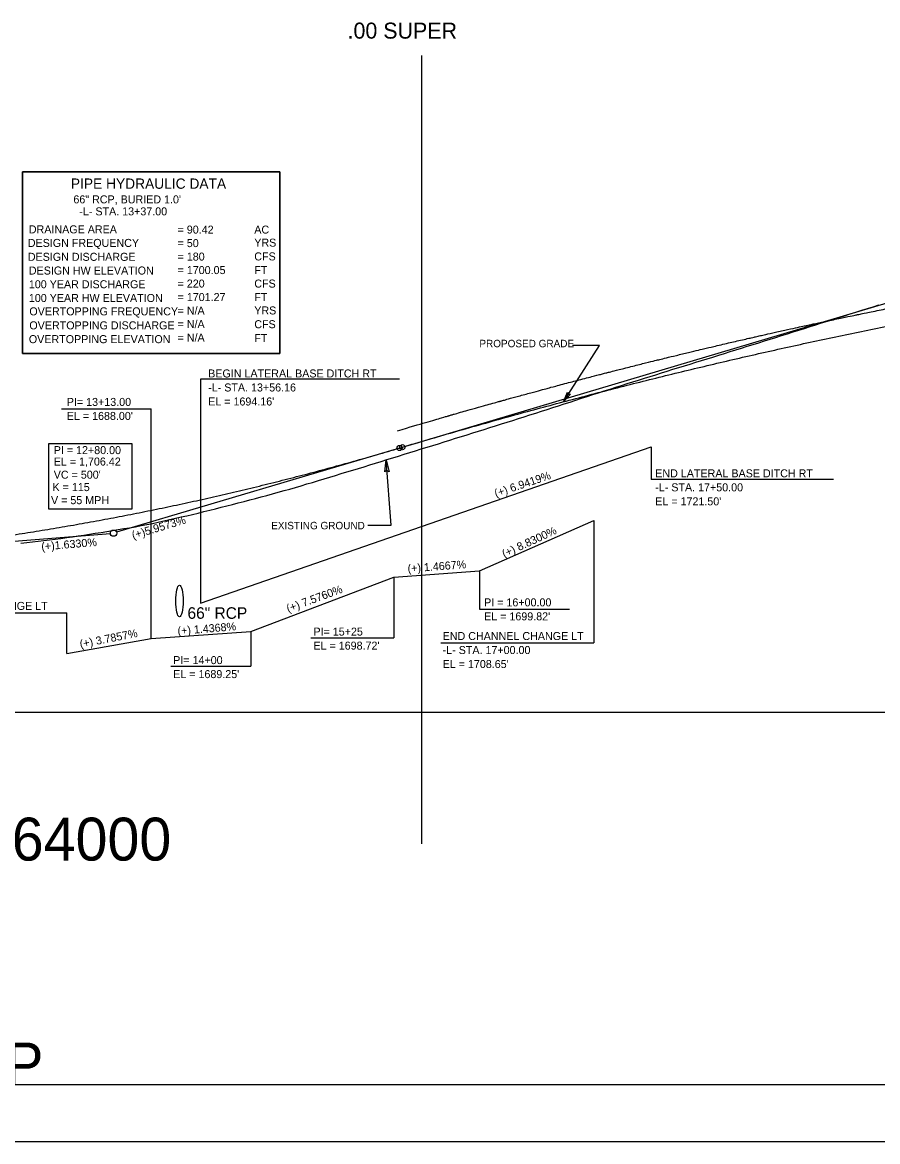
# Model space of a CAD drawing. Extents: x 498575 to 532350, y 405181 to 484585.
# Drawn here: x 506019 to 506767, y 483234 to 484213 of the extents above; entities that cross this region are included whole.
import ezdxf

# ---------------------------------------------------------------- set-up
doc = ezdxf.new("R2010")
doc.units = 0
for name, color, linetype in [('Exist Profile Cell', 7, 'Continuous'), ('Exist Vertical Profile Ground Line', 7, 'Continuous'), ('Prop Drainage Structure Pipe Welded Steel 54in Label', 7, 'Continuous'), ('Prop Grid Mask', 7, 'Continuous'), ('Prop PFL Text', 7, 'Continuous'), ('Prop Vertical Profile Curve Label', 7, 'Continuous'), ('Prop Vertical Profile Ditch Grade Left', 7, 'Continuous'), ('Prop Vertical Profile Ditch Grade Left Label', 7, 'Continuous'), ('Prop Vertical Profile Ditch Grade Right', 7, 'Continuous'), ('Prop Vertical Profile Ditch Grade Right Label', 7, 'Continuous'), ('Prop Vertical Profile Grade', 7, 'Continuous'), ('Prop Vertical Profile Grade Label', 7, 'Continuous'), ('Prop VPI Label', 7, 'Continuous'), ('Scratch_Level_4', 7, 'Continuous'), ('Scratch_Level_5', 7, 'Continuous'), ('Sheet Data Text CELL', 7, 'Continuous')]:
    doc.layers.add(name, color=color, linetype=linetype)

msp = doc.modelspace()

# ---------------------------------------------------------------- linework, layer by layer
at = {"layer": 'Exist Profile Cell'}
msp.add_line((505856.74, 483233.71), (526056.74, 483233.71), dxfattribs=at)
at = {"layer": 'Exist Vertical Profile Ground Line'}
for points in [[(506313.15, 483822.41), (506318.15, 483823.92), (506323.15, 483825.51), (506328.15, 483827.07), (506333.15, 483828.61), (506338.15, 483830.16), (506343.15, 483831.72), (506348.15, 483833.26), (506353.15, 483834.81), (506358.15, 483836.38), (506363.15, 483837.93), (506368.15, 483839.47), (506373.15, 483841.01), (506378.15, 483842.56), (506383.15, 483844.07), (506388.15, 483845.66), (506393.15, 483847.23), (506398.15, 483848.81), (506403.15, 483850.35), (506408.15, 483851.92), (506413.15, 483853.44), (506418.15, 483855.01), (506423.15, 483856.56), (506428.15, 483858.13), (506433.15, 483859.71), (506438.15, 483861.31), (506443.15, 483862.9), (506448.15, 483864.49), (506453.15, 483866.09), (506458.15, 483867.66), (506463.15, 483869.24), (506468.15, 483870.81), (506473.15, 483872.38), (506478.15, 483873.98), (506483.15, 483875.59), (506488.15, 483877.18), (506493.15, 483878.84), (506498.15, 483880.46), (506503.15, 483882.13), (506508.15, 483883.78), (506513.15, 483885.39), (506518.15, 483887.01), (506523.15, 483888.62), (506528.15, 483890.18), (506533.15, 483891.8), (506538.15, 483893.38), (506543.15, 483894.98), (506548.15, 483896.59), (506553.15, 483898.18), (506558.15, 483899.77), (506563.15, 483901.34), (506568.15, 483902.88), (506573.15, 483904.44), (506578.15, 483906.02), (506583.15, 483907.59), (506588.15, 483909.14), (506593.15, 483910.65), (506598.15, 483912.22), (506603.15, 483913.77), (506608.15, 483915.31), (506613.15, 483916.8), (506618.15, 483918.35), (506623.15, 483919.88), (506628.15, 483921.43), (506633.15, 483923.02), (506638.15, 483924.6), (506643.15, 483926.19), (506648.15, 483927.74), (506653.15, 483929.28), (506658.15, 483930.86), (506663.15, 483932.41), (506668.15, 483933.92), (506673.15, 483935.48), (506678.15, 483937.06), (506683.15, 483938.63), (506688.15, 483940.25), (506693.15, 483941.82), (506698.15, 483943.4), (506703.15, 483944.96), (506708.15, 483946.52), (506713.15, 483948.1), (506718.15, 483949.69), (506723.15, 483951.23), (506728.15, 483952.8), (506733.15, 483954.39), (506738.15, 483955.99), (506743.15, 483957.56), (506748.15, 483959.15), (506753.15, 483960.74), (506758.15, 483962.35), (506763.15, 483963.91), (506768.15, 483965.46)], [(506018.15, 483757.04), (506023.15, 483757.62), (506028.15, 483758.2), (506033.15, 483758.75), (506038.15, 483759.31), (506043.15, 483759.92), (506048.15, 483760.56), (506053.15, 483761.26), (506058.15, 483761.92), (506063.15, 483762.64), (506068.15, 483763.36), (506073.15, 483764.13), (506078.15, 483764.92), (506083.15, 483765.72), (506088.15, 483766.49), (506093.15, 483767.33), (506098.15, 483768.16), (506103.15, 483768.97), (506108.15, 483769.8), (506113.15, 483770.62), (506118.15, 483771.5), (506123.15, 483772.39), (506128.15, 483773.37), (506133.15, 483774.38), (506138.15, 483775.46), (506143.15, 483776.62), (506148.15, 483777.79), (506153.15, 483778.9), (506158.15, 483780.01), (506163.15, 483781.12), (506168.15, 483782.26), (506173.15, 483783.41), (506178.15, 483784.66), (506183.15, 483785.93), (506188.15, 483787.2), (506193.15, 483788.45), (506198.15, 483789.73), (506203.15, 483791.01), (506208.15, 483792.28), (506213.15, 483793.56), (506218.15, 483794.87), (506223.15, 483796.19), (506228.15, 483797.53), (506233.15, 483798.86), (506238.15, 483800.21), (506243.15, 483801.58), (506248.15, 483803), (506253.15, 483804.43), (506258.15, 483805.87), (506263.15, 483807.35), (506268.15, 483808.83), (506273.15, 483810.24), (506278.15, 483811.84), (506283.15, 483813.34), (506288.15, 483814.84), (506293.15, 483816.36), (506298.15, 483817.87), (506303.15, 483819.38), (506308.15, 483820.87), (506313.15, 483822.41)]]:
    msp.add_lwpolyline(points, dxfattribs=at)
at = {"layer": 'Prop Drainage Structure Pipe Welded Steel 54in Label'}
msp.add_ellipse((506156.7, 483706.52), major_axis=(0, 13.75), ratio=0.236364, dxfattribs=at)
at = {"layer": 'Prop Grid Mask'}
for points in [[(506019.47, 484081.91), (506244.47, 484081.91), (506244.47, 483922.91), (506019.47, 483922.91)], [(506042.37, 483787.13), (506115.38, 483787.13), (506115.38, 483843.91), (506042.37, 483843.91)]]:
    msp.add_lwpolyline(points, close=True, dxfattribs=at)
at = {"layer": 'Prop PFL Text'}
for p, q in [((506492.34, 483880.73), (506523.87, 483929.92)), ((506523.87, 483929.92), (506500.45, 483929.92)), ((506341.83, 483772.87), (506337.35, 483829.91)), ((506321.47, 483772.87), (506341.83, 483772.87))]:
    msp.add_line(p, q, dxfattribs=at)
for points in [[(506498.45, 483887.52), (506492.34, 483880.73), (506495.82, 483889.24), (506496.56, 483887.41)], [(506336.37, 483819.35), (506337.34, 483829.91), (506340.02, 483819.58), (506338.06, 483820.77)]]:
    msp.add_lwpolyline(points, close=True, dxfattribs=at)
at = {"layer": 'Prop Vertical Profile Curve Label'}
for centre in [(506349.08, 483840.3), (506351.58, 483841.05)]:
    msp.add_circle(centre, 2.25, dxfattribs=at)
at = {"layer": 'Prop Vertical Profile Ditch Grade Left'}
msp.add_lwpolyline([(506058.23, 483660.46), (506132.08, 483673.71), (506219.08, 483679.96), (506344.08, 483727.31), (506419.08, 483732.81), (506519.08, 483776.96)], dxfattribs=at)
at = {"layer": 'Prop Vertical Profile Ditch Grade Left Label'}
for p, q in [((506053.7, 483874.54), (506132.08, 483874.54)), ((506132.08, 483673.71), (506132.08, 483874.54)), ((506519.08, 483776.96), (506519.08, 483669.88)), ((506344.08, 483727.31), (506344.08, 483674.41)), ((506419.08, 483732.81), (506419.08, 483699.39)), ((505905.91, 483696.18), (506058.23, 483696.18)), ((506058.23, 483660.46), (506058.23, 483696.18)), ((506419.08, 483699.39), (506497.71, 483699.39)), ((506219.08, 483679.96), (506219.08, 483649.5)), ((506271.68, 483674.41), (506344.08, 483674.41)), ((506385.23, 483669.88), (506519.08, 483669.88)), ((506149.07, 483649.5), (506219.08, 483649.5))]:
    msp.add_line(p, q, dxfattribs=at)
at = {"layer": 'Prop Vertical Profile Ditch Grade Right'}
msp.add_line((506175.24, 483704.51), (506569.08, 483841.21), dxfattribs=at)
at = {"layer": 'Prop Vertical Profile Ditch Grade Right Label'}
for p, q in [((506349.12, 483900.4), (506175.24, 483900.4)), ((506175.24, 483900.4), (506175.24, 483704.51)), ((506569.08, 483841.21), (506569.08, 483812.74)), ((506728.41, 483812.74), (506569.08, 483812.74))]:
    msp.add_line(p, q, dxfattribs=at)
at = {"layer": 'Prop Vertical Profile Grade'}
msp.add_line((506349.08, 483840.3), (506351.58, 483841.05), dxfattribs=at)
for points in [[(506351.58, 483841.05), (506396.48, 483854.19), (506441.38, 483866.88), (506486.28, 483879.11), (506531.18, 483890.88), (506576.08, 483902.2), (506620.98, 483913.06), (506665.88, 483923.46), (506710.78, 483933.4), (506755.68, 483942.89), (506800.58, 483951.92), (506845.48, 483960.49), (506890.38, 483968.6), (506935.28, 483976.26), (506980.18, 483983.46), (507025.08, 483990.2), (507069.98, 483996.48), (507114.88, 484002.31), (507159.78, 484007.68), (507204.68, 484012.59), (507249.58, 484017.05), (507294.48, 484021.05), (507339.38, 484024.59), (507384.28, 484027.67), (507429.18, 484030.29), (507474.08, 484032.46), (507518.98, 484034.17), (507563.88, 484035.42), (507608.78, 484036.22), (507653.68, 484036.56), (507698.58, 484036.44), (507743.48, 484035.86), (507788.38, 484034.83), (507833.28, 484033.33), (507878.18, 484031.39), (507923.08, 484028.98), (507967.98, 484026.11), (508012.88, 484022.79), (508057.78, 484019.01), (508102.68, 484014.78), (508147.58, 484010.09), (508192.48, 484004.93), (508237.38, 483999.33), (508282.28, 483993.26), (508327.18, 483986.74), (508372.08, 483979.76), (508416.98, 483972.32), (508461.88, 483964.42), (508506.78, 483956.07), (508551.68, 483947.26), (508596.58, 483937.99)], [(505849.08, 483745.42), (505859.08, 483746.26), (505869.08, 483747.14), (505879.08, 483748.07), (505889.08, 483749.04), (505899.08, 483750.05), (505909.08, 483751.1), (505919.08, 483752.2), (505929.08, 483753.34), (505939.08, 483754.52), (505949.08, 483755.75), (505959.08, 483757.02), (505969.08, 483758.33), (505979.08, 483759.69), (505989.08, 483761.09), (505999.08, 483762.54), (506009.08, 483764.02), (506019.08, 483765.55), (506029.08, 483767.13), (506039.08, 483768.74), (506049.08, 483770.4), (506059.08, 483772.1), (506069.08, 483773.85), (506079.08, 483775.64), (506089.08, 483777.47), (506099.08, 483779.35), (506109.08, 483781.27), (506119.08, 483783.23), (506129.08, 483785.24), (506139.08, 483787.29), (506149.08, 483789.38), (506159.08, 483791.51), (506169.08, 483793.69), (506179.08, 483795.91), (506189.08, 483798.18), (506199.08, 483800.49), (506209.08, 483802.84), (506219.08, 483805.23), (506229.08, 483807.67), (506239.08, 483810.15), (506249.08, 483812.68), (506259.08, 483815.25), (506269.08, 483817.86), (506279.08, 483820.51), (506289.08, 483823.21), (506299.08, 483825.95), (506309.08, 483828.73), (506319.08, 483831.56), (506329.08, 483834.43), (506339.08, 483837.35), (506349.08, 483840.3)]]:
    msp.add_spline(points, degree=3, dxfattribs=at)
at = {"layer": 'Prop VPI Label'}
for p, q in [((506351.58, 483841.05), (507471.44, 484174.62)), ((506349.08, 483840.3), (506101.71, 483766.62)), ((505849.08, 483745.42), (506096.34, 483765.61))]:
    msp.add_line(p, q, dxfattribs=at)
msp.add_circle((506099.08, 483765.84), 2.75, dxfattribs=at)
at = {"layer": 'Scratch_Level_4'}
for p, q in [((506368.26, 484183.71), (506368.26, 483494.24)), ((505856.74, 483283.71), (512195.09, 483283.71))]:
    msp.add_line(p, q, dxfattribs=at)
at = {"layer": 'Scratch_Level_5'}
msp.add_line((513582.6, 483608.99), (498575.1, 483608.99), dxfattribs=at)
msp.add_open_spline([(506347.36, 483855.44), (506358.71, 483858.77), (506372.9, 483862.92), (506387.8, 483867.28), (506391.39, 483868.33), (506392.17, 483868.56), (506392.24, 483868.58), (506392.27, 483868.59), (506392.28, 483868.59), (506392.3, 483868.6), (506392.4, 483868.63), (506392.68, 483868.71), (506393.31, 483868.89), (506395.28, 483869.47), (506397.07, 483869.99), (506404.23, 483872.06), (506409.95, 483873.68), (506421.39, 483876.9), (506427.1, 483878.48), (506434.23, 483880.46), (506435.66, 483880.86), (506437.17, 483881.28), (506437.26, 483881.3), (506437.39, 483881.34), (506437.44, 483881.35), (506437.53, 483881.38), (506437.75, 483881.44), (506438.33, 483881.6), (506439.58, 483881.95), (506443.51, 483883.04), (506452.81, 483885.6), (506464.25, 483888.72), (506472.84, 483891.04), (506478.57, 483892.58), (506481.44, 483893.35), (506495.77, 483897.17), (506507.24, 483900.19), (506521.6, 483903.91), (506524.47, 483904.65), (506528.78, 483905.76), (506530.22, 483906.13), (506533.09, 483906.86), (506540.28, 483908.7), (506553.22, 483911.97), (506564.73, 483914.85), (506573.37, 483916.98), (506576.25, 483917.69), (506582.01, 483919.11), (506590.65, 483921.22), (506602.19, 483924), (506610.84, 483926.07), (506616.61, 483927.44), (506619.5, 483928.12), (506633.94, 483931.53), (506645.5, 483934.2), (506658.51, 483937.17), (506659.96, 483937.5), (506662.85, 483938.15), (506664.3, 483938.48), (506668.64, 483939.46), (506677.32, 483941.41), (506688.91, 483943.99), (506697.6, 483945.89), (506703.4, 483947.15), (506706.3, 483947.78), (506715, 483949.66), (506726.6, 483952.14), (506739.66, 483954.89), (506746.92, 483956.4), (506749.83, 483957), (506751.28, 483957.3), (506755.64, 483958.2), (506770.17, 483961.18), (506784.71, 483964.09), (506799.27, 483966.95), (506802.18, 483967.52), (506808.01, 483968.65), (506816.74, 483970.34), (506828.4, 483972.56), (506837.15, 483974.2), (506842.98, 483975.28), (506845.9, 483975.82), (506854.65, 483977.44), (506866.33, 483979.57), (506878.01, 483981.65), (506886.77, 483983.2), (506889.69, 483983.71), (506895.54, 483984.73), (506898.46, 483985.24), (506913.08, 483987.76), (506924.78, 483989.74), (506948.2, 483993.59), (506959.92, 483995.47), (506974.57, 483997.77), (506977.51, 483998.22), (506983.37, 483999.13), (506992.17, 484000.48), (507000.97, 484001.81), (507012.71, 484003.56), (507018.58, 484004.42), (507030.32, 484006.12), (507042.07, 484007.79), (507053.83, 484009.42), (507062.64, 484010.63), (507065.58, 484011.03), (507071.47, 484011.82), (507086.17, 484013.79), (507100.88, 484015.68), (507115.6, 484017.52), (507118.55, 484017.88), (507124.44, 484018.61), (507133.27, 484019.68), (507145.06, 484021.08), (507153.9, 484022.11), (507159.79, 484022.78), (507162.74, 484023.12), (507171.59, 484024.11), (507183.38, 484025.42), (507195.18, 484026.68), (507204.04, 484027.61), (507206.99, 484027.92), (507212.89, 484028.52), (507221.75, 484029.42), (507233.56, 484030.59), (507242.42, 484031.44), (507248.33, 484032), (507251.28, 484032.27), (507266.05, 484033.64), (507277.87, 484034.69), (507292.66, 484035.95), (507295.61, 484036.19), (507301.53, 484036.68), (507310.4, 484037.41), (507322.23, 484038.34), (507331.11, 484039.01), (507337.02, 484039.45), (507339.98, 484039.67), (507348.86, 484040.32), (507360.7, 484041.15), (507372.54, 484041.94), (507384.39, 484042.71), (507390.31, 484043.08), (507402.15, 484043.8), (507408.08, 484044.15), (507419.93, 484044.82), (507425.85, 484045.14), (507443.63, 484046.08), (507455.49, 484046.65), (507473.27, 484047.44), (507479.2, 484047.7), (507491.06, 484048.18), (507496.99, 484048.4), (507508.85, 484048.84), (507514.78, 484049.04), (507526.64, 484049.43), (507538.51, 484049.79), (507550.37, 484050.1), (507562.24, 484050.39), (507568.17, 484050.53), (507585.97, 484050.89), (507597.84, 484051.08), (507621.57, 484051.38), (507633.44, 484051.48), (507657.18, 484051.58), (507669.05, 484051.58), (507692.78, 484051.49), (507704.65, 484051.4), (507722.45, 484051.19), (507728.39, 484051.11), (507740.25, 484050.92), (507746.19, 484050.82), (507763.99, 484050.46), (507775.85, 484050.18), (507799.58, 484049.52), (507811.44, 484049.14), (507829.24, 484048.5), (507835.17, 484048.28), (507847.03, 484047.8), (507858.88, 484047.31), (507870.74, 484046.76), (507882.59, 484046.19), (507888.52, 484045.89), (507900.37, 484045.28), (507906.3, 484044.96), (507918.15, 484044.29), (507924.07, 484043.95), (507941.84, 484042.88), (507953.69, 484042.12), (507971.45, 484040.91), (507977.37, 484040.5), (507989.21, 484039.65), (507995.13, 484039.21), (508006.96, 484038.31), (508012.88, 484037.84), (508024.71, 484036.9), (508036.53, 484035.92), (508048.36, 484034.91), (508057.23, 484034.12), (508060.18, 484033.86), (508066.09, 484033.33), (508074.96, 484032.52), (508086.77, 484031.41), (508095.63, 484030.55), (508101.54, 484029.97), (508104.49, 484029.67), (508119.25, 484028.19), (508131.05, 484026.96), (508145.8, 484025.37), (508148.75, 484025.05), (508154.65, 484024.4), (508163.5, 484023.41), (508175.29, 484022.07), (508184.13, 484021.03), (508190.02, 484020.33), (508192.97, 484019.98), (508201.81, 484018.92), (508213.59, 484017.48), (508225.36, 484016), (508234.19, 484014.86), (508237.13, 484014.48), (508243.02, 484013.72), (508257.73, 484011.79), (508272.42, 484009.79), (508287.12, 484007.73), (508290.05, 484007.31), (508295.93, 484006.48), (508304.74, 484005.22), (508316.48, 484003.5), (508325.28, 484002.19), (508331.15, 484001.31), (508334.09, 484000.86), (508342.89, 483999.53), (508354.61, 483997.72), (508366.34, 483995.87), (508378.05, 483993.99), (508383.91, 483993.04), (508395.62, 483991.12), (508401.48, 483990.15), (508413.18, 483988.18), (508419.03, 483987.19), (508436.57, 483984.17), (508448.26, 483982.12), (508462.86, 483979.49), (508465.78, 483978.96), (508471.61, 483977.9), (508480.37, 483976.3), (508492.04, 483974.13), (508502.24, 483972.2), (508506.98, 483971.3), (508508.8, 483970.96), (508509.34, 483970.85), (508509.53, 483970.82), (508509.89, 483970.75), (508510.8, 483970.57), (508511.7, 483970.4), (508518.24, 483969.15), (508524.07, 483968.03), (508535.73, 483965.77), (508541.57, 483964.62), (508548.87, 483963.14), (508550.33, 483962.85), (508552.53, 483962.4), (508553.44, 483962.21), (508554.4, 483962.01), (508554.63, 483961.97), (508554.72, 483961.95), (508554.76, 483961.94), (508554.9, 483961.91), (508555.35, 483961.82), (508558.7, 483961.13), (508573.54, 483958.06), (508588.02, 483955.07), (508599.61, 483952.68)], degree=3, dxfattribs=at)
at = {"layer": 'Sheet Data Text CELL'}
msp.add_lwpolyline([(506019.47, 483922.91), (506244.47, 483922.91), (506244.47, 484081.91), (506019.47, 484081.91)], close=True, dxfattribs=at)

# ---------------------------------------------------------------- texts
at = {"layer": 'Exist Profile Cell'}
for s, p in [('1037.664000', (505856.74, 483479.51)), ('NOGAP', (505856.74, 483282.87))]:
    msp.add_text(s, height=37.5, dxfattribs=at).set_placement(p)
at = {"layer": 'Prop Drainage Structure Pipe Welded Steel 54in Label'}
msp.add_text('66" RCP', height=10.125, dxfattribs=at).set_placement((506163.74, 483690.91))
at = {"layer": 'Prop PFL Text'}
for s, p in [('PROPOSED GRADE', (506418.94, 483928.42)), ('EXISTING GROUND', (506236.93, 483769.22))]:
    msp.add_text(s, height=6.5157, dxfattribs=at).set_placement(p)
at = {"layer": 'Prop Vertical Profile Curve Label'}
for s, p in [("VC = 500'", (506046.81, 483813.47)), ('K = 115', (506045.75, 483802.63)), ('V = 55 MPH ', (506044.44, 483791.2))]:
    msp.add_text(s, height=7, dxfattribs=at).set_placement(p)
at = {"layer": 'Prop Vertical Profile Ditch Grade Left Label'}
for s, rotation, p in [('PI= 13+13.00', 360, (506058.22, 483877.1)), ("EL = 1688.00'", 360, (506058.22, 483864.85)), ('(+) 8.8300%', 24.83808, (506440.67, 483744.17)), ('(+) 1.4667%', 4.20337, (506356.42, 483731.43)), ('(+) 7.5760%', 20.15498, (506251.78, 483696.37)), ('BEGIN CHANNEL CHANGE LT', 360, (505908.89, 483698.7)), ('PI = 16+00.00', 360, (506423.06, 483701.81)), ("EL = 1699.82'", 360, (506423.06, 483689.56)), ('(+) 1.4368%', 4.60611, (506155.33, 483676.83)), ('(+) 3.7857%', 11.04903, (506070.24, 483665.37)), ('PI= 15+25', 360, (506273.85, 483676.23)), ('END CHANNEL CHANGE LT', 360, (506386.81, 483672.37)), ("EL = 1698.72'", 360, (506273.85, 483663.98)), ('-L- STA. 17+00.00', 360, (506386.81, 483660.12)), ('PI= 14+00', 360, (506151.24, 483651.32)), ("EL = 1708.65'", 360, (506386.81, 483647.87)), ("EL = 1689.25'", 360, (506151.24, 483639.07))]:
    msp.add_text(s, height=7, rotation=rotation, dxfattribs=at).set_placement(p)
at = {"layer": 'Prop Vertical Profile Ditch Grade Right Label'}
for s, rotation, p in [('BEGIN LATERAL BASE DITCH RT', 360, (506181.84, 483902)), ('-L- STA. 13+56.16', 360, (506181.84, 483889.75)), ("EL = 1694.16'", 360, (506181.84, 483877.5)), ('END LATERAL BASE DITCH RT', 360, (506572.67, 483814.66)), ('(+) 6.9419%', 18.64339, (506433.43, 483797.08)), ('-L- STA. 17+50.00', 360, (506572.67, 483802.41)), ("EL = 1721.50'", 360, (506572.67, 483790.16))]:
    msp.add_text(s, height=7, rotation=rotation, dxfattribs=at).set_placement(p)
at = {"layer": 'Prop Vertical Profile Grade Label'}
for s, rotation, p in [('(+)5.9573%', 16.58697, (506116.24, 483760.51)), ('(+)1.6330%', 4.66793, (506036.24, 483750.67))]:
    msp.add_text(s, height=7, rotation=rotation, dxfattribs=at).set_placement(p)
at = {"layer": 'Prop VPI Label'}
for s, p in [('PI = 12+80.00', (506046.81, 483834.96)), ('EL = 1,706.42', (506046.81, 483824.96))]:
    msp.add_text(s, height=7, dxfattribs=at).set_placement(p)
at = {"layer": 'Scratch_Level_4'}
msp.add_text('.00 SUPER', height=14, dxfattribs=at).set_placement((506303.66, 484198.32))
at = {"layer": 'Sheet Data Text CELL'}
for s, height, p in [('PIPE HYDRAULIC DATA', 8.9997, (506061.77, 484067.02)), ('DRAINAGE AREA', 6.9999, (506025.05, 484028.01)), ('= 90.42', 7, (506155.08, 484027.81)), ('AC', 7, (506222.14, 484027.81)), ('DESIGN FREQUENCY', 6.9999, (506024.15, 484016.16)), ('= 50', 7, (506155.08, 484016.01)), ('YRS', 7, (506222.14, 484016.41)), ('DESIGN DISCHARGE', 6.9999, (506024.15, 484004.01)), ('= 180', 7, (506155.08, 484004.21)), ('CFS', 7, (506222.14, 484004.36)), ('DESIGN HW ELEVATION', 6.9999, (506025.05, 483992.01)), ('= 1700.05', 7, (506155.08, 483992.41)), ('FT', 7, (506222.14, 483992.41)), ('= 220', 7, (506155.08, 483980.61)), ('CFS', 7, (506222.14, 483980.61)), ('100 YEAR DISCHARGE', 6.9999, (506025.05, 483980.01)), ('100 YEAR HW ELEVATION', 6.9999, (506025.05, 483968.01)), ('= 1701.27', 7, (506155.08, 483968.81)), ('FT', 7, (506222.14, 483968.81)), ('OVERTOPPING FREQUENCY', 6.9999, (506025.5, 483956.31)), ('= N/A', 7, (506155.08, 483957.01)), ('YRS', 7, (506222.14, 483957.11)), ('OVERTOPPING DISCHARGE', 6.9999, (506025.5, 483944.06)), ('= N/A', 7, (506155.08, 483945.21)), ('CFS', 7, (506222.14, 483945.06)), ('OVERTOPPING ELEVATION', 6.9999, (506025.05, 483932.01)), ('= N/A', 7, (506155.08, 483933.41)), ('FT', 7, (506222.14, 483933.01))]:
    msp.add_text(s, height=height, rotation=360, dxfattribs=at).set_placement(p)
for s, p in [('     66" RCP, BURIED 1.0\'', (506050.99, 484054.25)), ('   -L- STA. 13+37.00', (506061.39, 484043.75))]:
    msp.add_text(s, height=7, dxfattribs=at).set_placement(p)

doc.saveas('drawing.dxf')
